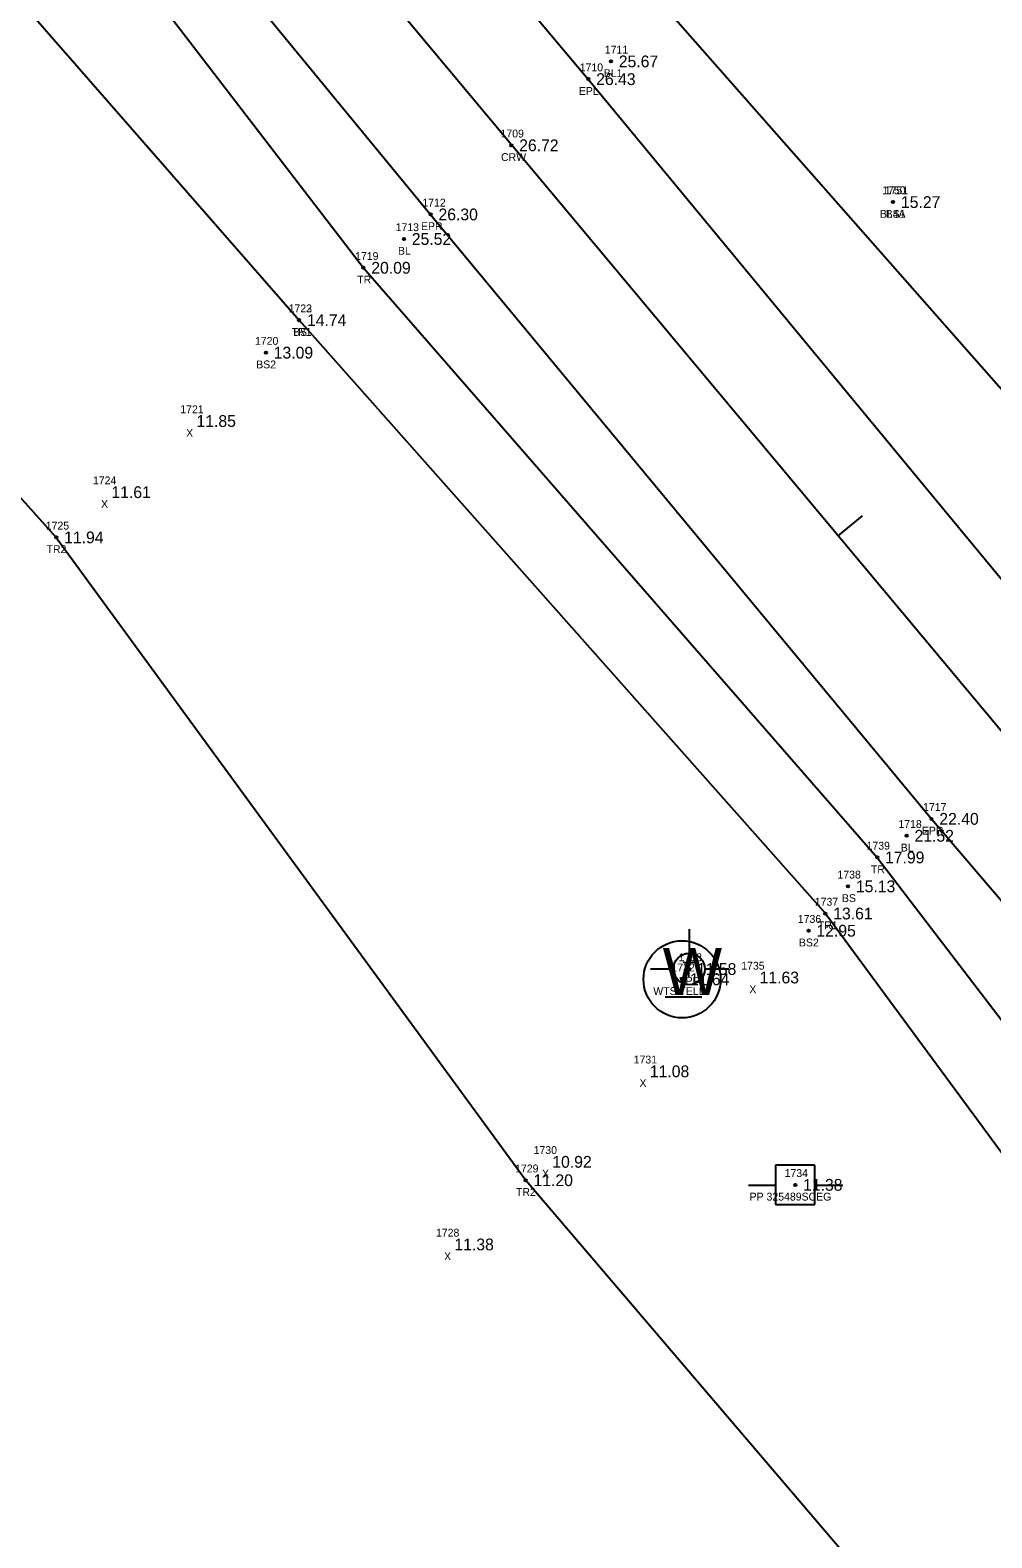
# Model space of a CAD drawing. Extents: x 2042117 to 2045853, y 303080 to 309569.
# Drawn here: x 2043814.7 to 2043937.2, y 305237.3 to 305429.3 of the extents above; entities that cross this region are included whole.
import ezdxf

# ---------------------------------------------------------------- set-up
doc = ezdxf.new("R2010")
doc.units = 0
for name, color, linetype in [('RD_DTM_BkLn_txCode', 7, 'Continuous'), ('RD_EX_Misc_txCode', 7, 'Continuous'), ('RD_EX_Road', 7, 'Continuous'), ('RD_EX_Road_txCode', 7, 'Continuous'), ('RD_EX_TX_Misc_ELEV', 7, 'Continuous'), ('RD_EX_TX_Road_ELEV', 7, 'Continuous'), ('RD_EX_TX_UT_ELEV', 7, 'Continuous'), ('RD_EX_TX_VEG_ELEV', 7, 'Continuous'), ('RD_EX_UT', 7, 'Continuous'), ('RD_EX_UT_txCode', 7, 'Continuous'), ('RD_EX_VEG', 7, 'Continuous'), ('RD_EX_VEG_txCode', 7, 'Continuous'), ('RD_HC_Cl', 7, 'Continuous'), ('RD_HC_Data_Tic', 7, 'Continuous'), ('RD_HC_Survey_ELEV', 7, 'Continuous'), ('RD_HC_Survey_txCode', 7, 'Continuous'), ('RD_SMD_Locator', 7, 'Continuous')]:
    doc.layers.add(name, color=color, linetype=linetype)

msp = doc.modelspace()

# ---------------------------------------------------------------- linework, layer by layer
at = {"layer": 'RD_EX_Road'}
for points in [[(2043522.11, 305820), (2043547.67, 305789.85), (2043610.72, 305713.32), (2043674.95, 305636.32), (2043738.18, 305559.62), (2043802.42, 305482.71), (2043865.72, 305405.84), (2043929.53, 305328.85), (2043994.13, 305253.28), (2044057.4, 305176.5), (2044121.27, 305100.2), (2044185.29, 305023.54), (2044249.56, 304947.28), (2044313.31, 304870.31), (2044377.09, 304793.29), (2044442, 304716.26), (2044505.92, 304639.55), (2044570.44, 304562.35), (2044634.61, 304485.93), (2044698.46, 304409.27), (2044762.46, 304332.37)], [(2043821.87, 305499.1), (2043885.81, 305423.07), (2043949.56, 305345.93), (2044013.41, 305270.34), (2044077.97, 305194.15), (2044141.4, 305117.67), (2044205.92, 305040.83), (2044269.54, 304964.65), (2044331.73, 304891.04), (2044335.22, 304889.2), (2044346.01, 304875.31), (2044356.18, 304867.61), (2044370.01, 304868.14), (2044386.83, 304866.36), (2044389.44, 304849.53), (2044390.71, 304830.73), (2044393.77, 304818.44), (2044395.5, 304814.18), (2044398.16, 304811.09)]]:
    msp.add_lwpolyline(points, dxfattribs=at)
at = {"layer": 'RD_EX_UT'}
for p, q in [((2043898.65, 305314.79), (2043898.65, 305311.72)), ((2043893.72, 305309.74), (2043896.65, 305309.74)), ((2043900.65, 305309.74), (2043903.72, 305309.74)), ((2043895.62, 305306.2), (2043900.25, 305306.2)), ((2043914.66, 305284.74), (2043909.66, 305284.74)), ((2043909.66, 305284.74), (2043909.66, 305279.74)), ((2043914.66, 305279.74), (2043914.66, 305284.74)), ((2043906.23, 305282.18), (2043909.7, 305282.18)), ((2043914.59, 305282.18), (2043918.23, 305282.18)), ((2043909.66, 305279.74), (2043914.66, 305279.74))]:
    msp.add_line(p, q, dxfattribs=at)
for centre, radius in [((2043897.75, 305308.41), 4.91), ((2043898.65, 305309.72), 2)]:
    msp.add_circle(centre, radius, dxfattribs=at)
at = {"layer": 'RD_EX_VEG'}
for points in [[(2043547.51, 305881.5), (2043539.7, 305861.32), (2043541.74, 305855.07), (2043567.73, 305828.7), (2043642.4, 305738.29), (2043706.88, 305661.84), (2043768.33, 305586.86), (2043834.29, 305506.38), (2043895.63, 305432.16), (2043964.52, 305353.99), (2044012.41, 305288.23), (2044020.96, 305286.08), (2044026.64, 305287.13), (2044039.88, 305282.36)], [(2043510.52, 305810.42), (2043502.87, 305810.61), (2043504.87, 305802.25), (2043509.11, 305791.37), (2043594.27, 305695.69), (2043658.16, 305620.89), (2043717.86, 305542.89), (2043784.35, 305466.31), (2043848.97, 305392.37), (2043916.01, 305316.79), (2043971.98, 305240.84)], [(2043510.52, 305810.42), (2043528.58, 305788.55), (2043603.52, 305706.8), (2043669.11, 305631.48), (2043746.08, 305529.27), (2043781.83, 305496.01), (2043793.11, 305482.33), (2043857.16, 305399.04), (2043922.61, 305323.93), (2043978.69, 305250.66), (2043978.39, 305246.16), (2043971.98, 305240.84)], [(2043442.97, 305737.07), (2043459.87, 305757.29), (2043500.33, 305735.55), (2043510.29, 305716.16), (2043558.94, 305666.15), (2043625.65, 305592.92), (2043688.91, 305518.94), (2043753.11, 305437.19), (2043818.03, 305364.7), (2043877.83, 305282.82), (2043938.63, 305211.62), (2044011.48, 305138.99), (2044075.86, 305057.44), (2044138.75, 304984.38), (2044203.27, 304905.13), (2044266.06, 304829.27), (2044328.58, 304748.23), (2044394.11, 304672.51), (2044456.79, 304595.02), (2044489.64, 304560.38)]]:
    msp.add_lwpolyline(points, dxfattribs=at)
at = {"layer": 'RD_HC_Cl'}
msp.add_line((2043284.3, 306123.24), (2045221.31, 303804), dxfattribs=at)
at = {"layer": 'RD_HC_Data_Tic'}
msp.add_line((2043917.66, 305364.89), (2043920.73, 305367.46), dxfattribs=at)
at = {"layer": 'RD_SMD_Locator'}
for centre in [(2043888.69, 305425.33), (2043885.81, 305423.07), (2043876, 305414.64), (2043924.64, 305407.41), (2043924.64, 305407.41), (2043865.72, 305405.84), (2043862.32, 305402.71), (2043857.16, 305399.04), (2043848.97, 305392.37), (2043848.97, 305392.37), (2043844.73, 305388.23), (2043818.03, 305364.7), (2043929.53, 305328.85), (2043926.37, 305326.69), (2043922.61, 305323.93), (2043918.9, 305320.25), (2043916.01, 305316.79), (2043913.87, 305314.6), (2043897.75, 305308.41), (2043898.65, 305309.72), (2043877.83, 305282.82), (2043912.17, 305282.23)]:
    msp.add_circle(centre, 0.15, dxfattribs=at)

# ---------------------------------------------------------------- texts
at = {"layer": 'RD_DTM_BkLn_txCode'}
for s, p in [('1711', (2043887.91, 305426.33)), ('BL1', (2043887.77, 305423.33)), ('1750', (2043923.25, 305408.41)), ('1751', (2043923.58, 305408.41)), ('BL4A', (2043922.95, 305405.41)), ('BS1', (2043923.69, 305405.41)), ('1713', (2043861.26, 305403.71)), ('BL', (2043861.56, 305400.71)), ('1723', (2043847.63, 305393.37)), ('BS', (2043848.19, 305390.37)), ('1720', (2043843.34, 305389.23)), ('BS2', (2043843.5, 305386.23)), ('1718', (2043925.31, 305327.69)), ('BL', (2043925.62, 305324.69)), ('1738', (2043917.55, 305321.25)), ('BS', (2043918.12, 305318.25)), ('1736', (2043912.5, 305315.6)), ('BS2', (2043912.64, 305312.6))]:
    msp.add_text(s, height=1, dxfattribs=at).set_placement(p)
at = {"layer": 'RD_EX_Misc_txCode'}
for s, p in [('1721', (2043833.83, 305380.52)), ('X', (2043834.57, 305377.52)), ('1724', (2043822.7, 305371.46)), ('X', (2043823.73, 305368.46)), ('1735', (2043905.29, 305309.64)), ('X', (2043906.32, 305306.64)), ('1731', (2043891.59, 305297.69)), ('X', (2043892.33, 305294.69)), ('1730', (2043878.84, 305286.16)), ('X', (2043879.91, 305283.16)), ('1728', (2043866.4, 305275.64)), ('X', (2043867.43, 305272.64))]:
    msp.add_text(s, height=1, dxfattribs=at).set_placement(p)
at = {"layer": 'RD_EX_Road_txCode'}
for s, p in [('1710', (2043884.71, 305424.07)), ('EPL', (2043884.6, 305421.07)), ('1712', (2043864.66, 305406.84)), ('EPR', (2043864.49, 305403.84)), ('1717', (2043928.46, 305329.85)), ('EPR', (2043928.3, 305326.85))]:
    msp.add_text(s, height=1, dxfattribs=at).set_placement(p)
at = {"layer": 'RD_EX_TX_Misc_ELEV'}
for s, p in [('25.67', (2043889.69, 305424.58)), ('15.27', (2043925.64, 305406.66)), ('15.27', (2043925.64, 305406.66)), ('25.52', (2043863.32, 305401.96)), ('14.74', (2043849.97, 305391.62)), ('13.09', (2043845.73, 305387.48)), ('11.85', (2043835.89, 305378.77)), ('11.61', (2043825.05, 305369.71)), ('21.52', (2043927.37, 305325.94)), ('15.13', (2043919.9, 305319.5)), ('12.95', (2043914.87, 305313.85)), ('11.63', (2043907.63, 305307.89)), ('11.08', (2043893.65, 305295.94)), ('10.92', (2043881.22, 305284.41)), ('11.38', (2043868.75, 305273.89))]:
    msp.add_text(s, height=1.5, dxfattribs=at).set_placement(p)
at = {"layer": 'RD_EX_TX_Road_ELEV'}
for s, p in [('26.43', (2043886.81, 305422.32)), ('26.30', (2043866.72, 305405.09)), ('22.40', (2043930.53, 305328.1))]:
    msp.add_text(s, height=1.5, dxfattribs=at).set_placement(p)
at = {"layer": 'RD_EX_TX_UT_ELEV'}
for s, p in [('11.58', (2043899.65, 305308.97)), ('11.64', (2043898.75, 305307.66))]:
    msp.add_text(s, height=1.5, dxfattribs=at).set_placement(p)
at = {"layer": 'RD_EX_TX_VEG_ELEV'}
for s, p in [('20.09', (2043858.16, 305398.29)), ('14.74', (2043849.97, 305391.62)), ('11.94', (2043819.03, 305363.95)), ('17.99', (2043923.61, 305323.18)), ('13.61', (2043917.01, 305316.04)), ('11.20', (2043878.83, 305282.07))]:
    msp.add_text(s, height=1.5, dxfattribs=at).set_placement(p)
at = {"layer": 'RD_EX_UT'}
for s, height, p in [('W', 6, (2043895.28, 305306.41)), ('T', 2, (2043897.8, 305308.67))]:
    msp.add_text(s, height=height, dxfattribs=at).set_placement(p)
at = {"layer": 'RD_EX_UT_txCode'}
for s, p in [('1732', (2043896.4, 305309.41)), ('1733', (2043897.31, 305310.72)), ('TPP', (2043897.39, 305307.72)), ('WTS TELE', (2043894.09, 305306.41)), ('1734', (2043910.82, 305283.23)), ('PP 325489SCEG', (2043906.36, 305280.23))]:
    msp.add_text(s, height=1, dxfattribs=at).set_placement(p)
at = {"layer": 'RD_EX_VEG_txCode'}
for s, p in [('1719', (2043856.1, 305400.04)), ('TR', (2043856.37, 305397.04)), ('1722', (2043847.63, 305393.37)), ('TR1', (2043848.01, 305390.37)), ('1725', (2043816.69, 305365.7)), ('TR2', (2043816.79, 305362.7)), ('1739', (2043921.26, 305324.93)), ('TR', (2043921.81, 305321.93)), ('1737', (2043914.66, 305317.79)), ('TR1', (2043915.05, 305314.79)), ('1729', (2043876.48, 305283.82)), ('TR2', (2043876.59, 305280.82))]:
    msp.add_text(s, height=1, dxfattribs=at).set_placement(p)
at = {"layer": 'RD_HC_Survey_ELEV'}
for s, p in [('26.72', (2043877, 305413.89)), ('11.38', (2043913.17, 305281.48))]:
    msp.add_text(s, height=1.5, dxfattribs=at).set_placement(p)
at = {"layer": 'RD_HC_Survey_txCode'}
for s, p in [('1709', (2043874.62, 305415.64)), ('CRW', (2043874.69, 305412.64))]:
    msp.add_text(s, height=1, dxfattribs=at).set_placement(p)

doc.saveas('drawing.dxf')
